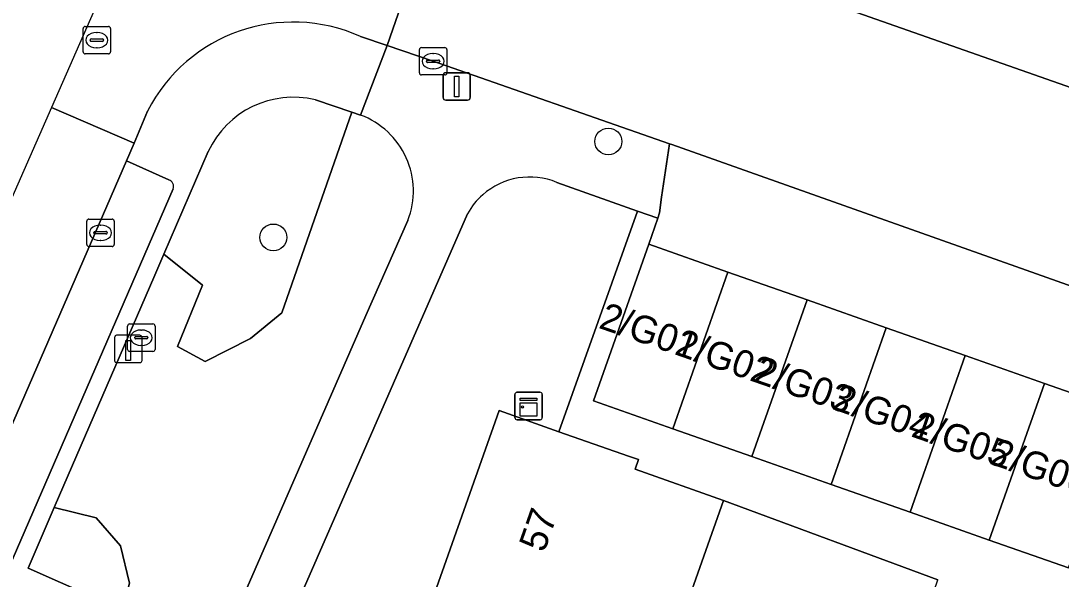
# Model space of a CAD drawing. Extents: x 163266 to 164362, y 381528 to 382286.
# Drawn here: x 163663.56 to 163701.49, y 381798.56 to 381818.93 of the extents above; entities that cross this region are included whole.
import ezdxf

# ---------------------------------------------------------------- set-up
doc = ezdxf.new("R2010")
doc.units = 0
for name, color, linetype in [('IMGEO_Boom', 7, 'Continuous'), ('IMGEO_Erf', 7, 'Continuous'), ('IMGEO_Groenvoorziening', 7, 'Continuous'), ('IMGEO_Kast', 7, 'Continuous'), ('IMGEO_Kolk', 7, 'Continuous'), ('IMGEO_Laadpaal', 7, 'Continuous'), ('IMGEO_Lichtmast', 7, 'Continuous'), ('IMGEO_Pand', 7, 'Continuous'), ('IMGEO_Pand_nummerreeks', 7, 'Continuous'), ('IMGEO_Parkeervlak_open', 7, 'Continuous'), ('IMGEO_Rijbaan_lokaal_open', 7, 'Continuous'), ('IMGEO_Rioolput', 7, 'Continuous'), ('IMGEO_Voetpad_open', 7, 'Continuous')]:
    doc.layers.add(name, color=color, linetype=linetype)

msp = doc.modelspace()

# ---------------------------------------------------------------- linework, layer by layer
at = {"layer": 'IMGEO_Boom'}
for centre in [(163684.985, 381814.526), (163672.771, 381811.027)]:
    msp.add_circle(centre, 0.489, dxfattribs=at)
at = {"layer": 'IMGEO_Erf'}
for points in [[(163666.153, 381762.56), (163668.236, 381768.474), (163670.319, 381774.388), (163672.403, 381780.302), (163674.486, 381786.216), (163676.569, 381792.13), (163678.652, 381798.043), (163681.001, 381804.712), (163683.186, 381803.942), (163686.047, 381811.989), (163683.111, 381813.033)], [(163679.851, 381811.893), (163653.323, 381751.193), (163653.198, 381750)], [(163689.96, 381777.195), (163692.927, 381776.181), (163695.11, 381782.57), (163692.014, 381783.644), (163692.619, 381785.386), (163692.838, 381786.018), (163692.983, 381786.435), (163693.974, 381789.288), (163697.139, 381788.189), (163697.285, 381788.135), (163699.434, 381794.32), (163695.961, 381795.52), (163697.003, 381798.534), (163689.18, 381801.438), (163686.959, 381795.132), (163684.876, 381789.218), (163682.793, 381783.305), (163680.71, 381777.391), (163678.626, 381771.476), (163676.543, 381765.562)]]:
    msp.add_lwpolyline(points, dxfattribs=at)
for centre, radius, start, end in [((163682.119, 381810.637), 2.593, 67.5074, 131.4104), ((163682.13, 381810.63), 2.606, 131.4888, 151.0092)]:
    msp.add_arc(centre, radius, start, end, dxfattribs=at)
at = {"layer": 'IMGEO_Groenvoorziening'}
for points in [[(163675.631, 381815.598), (163674.306, 381816.042)], [(163675.953, 381815.49), (163675.631, 381815.598), (163673.083, 381808.276), (163671.945, 381807.337), (163670.285, 381806.507), (163669.274, 381807.048), (163670.194, 381809.286), (163668.78, 381810.415), (163668.449, 381809.65), (163664.786, 381801.179), (163666.314, 381800.803), (163667.198, 381799.774), (163667.523, 381798.42), (163667.255, 381797.445), (163670.736, 381795.905), (163671.522, 381797.593), (163676.148, 381808.181)], [(163670.398, 381814.16), (163668.78, 381810.415), (163670.194, 381809.286), (163669.274, 381807.048), (163670.285, 381806.507), (163671.945, 381807.337), (163673.083, 381808.276), (163675.631, 381815.598)], [(163676.148, 381808.181), (163677.678, 381811.648)]]:
    msp.add_lwpolyline(points, dxfattribs=at)
msp.add_lwpolyline([(163664.786, 381801.179), (163663.828, 381798.962), (163667.255, 381797.445), (163667.523, 381798.42), (163667.198, 381799.774), (163666.314, 381800.803)], close=True, dxfattribs=at)
for centre, radius, start, end in [((163673.501, 381812.714), 3.424, 76.4087, 155.02), ((163674.914, 381812.715), 2.963, 338.8846, 69.4742)]:
    msp.add_arc(centre, radius, start, end, dxfattribs=at)
at = {"layer": 'IMGEO_Kast'}
for p, q in [((163681.577, 381804.454), (163681.577, 381805.295)), ((163681.577, 381805.295), (163681.577, 381804.454)), ((163681.652, 381805.379), (163682.493, 381805.379)), ((163682.493, 381805.379), (163681.652, 381805.379)), ((163682.577, 381805.304), (163682.577, 381804.463)), ((163682.577, 381804.463), (163682.577, 381805.304)), ((163682.502, 381804.379), (163681.661, 381804.379)), ((163681.661, 381804.379), (163682.502, 381804.379))]:
    msp.add_line(p, q, dxfattribs=at)
for points in [[(163681.772, 381805.169), (163682.372, 381805.169), (163682.372, 381805.084), (163681.772, 381805.084), (163681.772, 381805.169)], [(163681.772, 381804.994), (163682.372, 381804.994), (163682.372, 381804.505), (163681.772, 381804.505), (163681.772, 381804.994)]]:
    msp.add_lwpolyline(points, dxfattribs=at)
msp.add_circle((163681.856, 381804.843), 0.0377, dxfattribs=at)
for centre, start, end in [((163681.655, 381805.301), 92.4484, 184.2845), ((163681.655, 381805.301), 92.4484, 184.2845), ((163682.499, 381805.301), 2.4484, 94.2845), ((163682.499, 381805.301), 2.4484, 94.2845), ((163681.655, 381804.457), 182.4484, 274.2845), ((163681.655, 381804.457), 182.4484, 274.2845), ((163682.499, 381804.457), 272.4484, 4.2845), ((163682.499, 381804.457), 272.4484, 4.2845)]:
    msp.add_arc(centre, 0.0779, start, end, dxfattribs=at)
at = {"layer": 'IMGEO_Kolk'}
for p, q in [((163678.096, 381817.026), (163678.096, 381817.878)), ((163678.171, 381817.952), (163679.023, 381817.952)), ((163679.097, 381817.878), (163679.097, 381817.026)), ((163678.355, 381817.446), (163678.355, 381817.458)), ((163678.793, 381817.409), (163678.395, 381817.409)), ((163678.398, 381817.495), (163678.796, 381817.495)), ((163678.584, 381817.732), (163678.609, 381817.732)), ((163678.839, 381817.458), (163678.839, 381817.446)), ((163678.607, 381817.172), (163678.582, 381817.172)), ((163679.023, 381816.952), (163678.171, 381816.952)), ((163666.045, 381811.696), (163666.897, 381811.696)), ((163665.97, 381810.77), (163665.97, 381811.622)), ((163666.458, 381811.476), (163666.483, 381811.476)), ((163666.971, 381811.622), (163666.971, 381810.77)), ((163666.229, 381811.19), (163666.229, 381811.202)), ((163666.667, 381811.153), (163666.269, 381811.153)), ((163666.272, 381811.239), (163666.67, 381811.239)), ((163666.713, 381811.202), (163666.713, 381811.19)), ((163666.897, 381810.696), (163666.045, 381810.696)), ((163666.481, 381810.916), (163666.456, 381810.916)), ((163667.457, 381806.944), (163667.457, 381807.796)), ((163667.532, 381807.87), (163668.384, 381807.87)), ((163667.945, 381807.65), (163667.97, 381807.65)), ((163668.458, 381807.796), (163668.458, 381806.944)), ((163667.716, 381807.364), (163667.716, 381807.376)), ((163668.154, 381807.327), (163667.756, 381807.327)), ((163667.759, 381807.413), (163668.157, 381807.413)), ((163668.2, 381807.376), (163668.2, 381807.364)), ((163668.384, 381806.87), (163667.532, 381806.87)), ((163667.968, 381807.09), (163667.943, 381807.09))]:
    msp.add_line(p, q, dxfattribs=at)
for points in [[(163678.096, 381817.026), (163678.096, 381817.878)], [(163678.171, 381817.952), (163679.023, 381817.952)], [(163679.097, 381817.878), (163679.097, 381817.026)], [(163679.023, 381816.952), (163678.171, 381816.952)], [(163666.045, 381811.696), (163666.897, 381811.696)], [(163665.97, 381810.77), (163665.97, 381811.622)], [(163666.971, 381811.622), (163666.971, 381810.77)], [(163666.897, 381810.696), (163666.045, 381810.696)], [(163667.457, 381806.944), (163667.457, 381807.796)], [(163667.532, 381807.87), (163668.384, 381807.87)], [(163668.458, 381807.796), (163668.458, 381806.944)], [(163668.384, 381806.87), (163667.532, 381806.87)]]:
    msp.add_lwpolyline(points, dxfattribs=at)
for centre, radius, start, end in [((163678.173, 381817.876), 0.0765, 91.552, 178.448), ((163678.173, 381817.876), 0.0765, 91.552, 178.448), ((163679.021, 381817.876), 0.0765, 1.552, 88.448), ((163679.021, 381817.876), 0.0765, 1.552, 88.448), ((163678.395, 381817.455), 0.0403, 85.8775, 175.7526), ((163678.392, 381817.445), 0.0366, 178.938, 274.7102), ((163678.796, 381817.452), 0.043, 264.8664, 352.4533), ((163678.8, 381817.457), 0.0386, 1.7309, 96.639), ((163678.173, 381817.028), 0.0765, 181.552, 268.448), ((163678.173, 381817.028), 0.0765, 181.552, 268.448), ((163679.021, 381817.028), 0.0765, 271.552, 358.448), ((163679.021, 381817.028), 0.0765, 271.552, 358.448), ((163666.047, 381811.62), 0.0765, 91.552, 178.448), ((163666.047, 381811.62), 0.0765, 91.552, 178.448), ((163666.895, 381811.62), 0.0765, 1.552, 88.448), ((163666.895, 381811.62), 0.0765, 1.552, 88.448), ((163666.269, 381811.199), 0.0403, 85.8775, 175.7526), ((163666.266, 381811.189), 0.0366, 178.938, 274.7102), ((163666.67, 381811.196), 0.043, 264.8664, 352.4533), ((163666.674, 381811.201), 0.0386, 1.7309, 96.639), ((163666.047, 381810.772), 0.0765, 181.552, 268.448), ((163666.047, 381810.772), 0.0765, 181.552, 268.448), ((163666.895, 381810.772), 0.0765, 271.552, 358.448), ((163666.895, 381810.772), 0.0765, 271.552, 358.448), ((163667.534, 381807.794), 0.0765, 91.552, 178.448), ((163667.534, 381807.794), 0.0765, 91.552, 178.448), ((163668.382, 381807.794), 0.0765, 1.552, 88.448), ((163668.382, 381807.794), 0.0765, 1.552, 88.448), ((163667.756, 381807.373), 0.0403, 85.8775, 175.7526), ((163667.753, 381807.363), 0.0366, 178.938, 274.7102), ((163668.157, 381807.37), 0.043, 264.8664, 352.4533), ((163668.161, 381807.375), 0.0386, 1.7309, 96.639), ((163667.534, 381806.946), 0.0765, 181.552, 268.448), ((163667.534, 381806.946), 0.0765, 181.552, 268.448), ((163668.382, 381806.946), 0.0765, 271.552, 358.448), ((163668.382, 381806.946), 0.0765, 271.552, 358.448)]:
    msp.add_arc(centre, radius, start, end, dxfattribs=at)
for centre, major_axis, ratio, start_param, end_param in [((163678.583, 381817.452), (-0.387, 0.002), 0.722429, 4.712389, 7.853982), ((163678.608, 381817.452), (-0.39, 0.002), 0.717154, 1.570796, 4.712389), ((163666.457, 381811.196), (-0.387, 0.002), 0.722429, 4.712389, 7.853982), ((163666.482, 381811.196), (-0.39, 0.002), 0.717154, 1.570796, 4.712389), ((163667.944, 381807.37), (-0.387, 0.002), 0.722429, 4.712389, 7.853982), ((163667.969, 381807.37), (-0.39, 0.002), 0.717154, 1.570796, 4.712389)]:
    msp.add_ellipse(centre, major_axis=major_axis, ratio=ratio, start_param=start_param, end_param=end_param, dxfattribs=at)
at = {"layer": 'IMGEO_Laadpaal'}
for p, q in [((163666.984, 381807.376), (163666.984, 381806.535)), ((163666.984, 381807.376), (163666.984, 381806.535)), ((163667.9, 381807.46), (163667.059, 381807.46)), ((163667.9, 381807.46), (163667.059, 381807.46)), ((163667.984, 381806.544), (163667.984, 381807.385)), ((163667.984, 381806.544), (163667.984, 381807.385)), ((163667.068, 381806.46), (163667.909, 381806.46)), ((163667.068, 381806.46), (163667.909, 381806.46))]:
    msp.add_line(p, q, dxfattribs=at)
msp.add_lwpolyline([(163667.399, 381807.273), (163667.559, 381807.273), (163667.559, 381806.54), (163667.399, 381806.54), (163667.399, 381807.273)], dxfattribs=at)
for centre, start, end in [((163667.062, 381807.382), 92.4484, 184.2845), ((163667.062, 381807.382), 92.4484, 184.2845), ((163667.906, 381807.382), 2.4484, 94.2845), ((163667.906, 381807.382), 2.4484, 94.2845), ((163667.062, 381806.538), 182.4484, 274.2845), ((163667.062, 381806.538), 182.4484, 274.2845), ((163667.906, 381806.538), 272.4484, 4.2845), ((163667.906, 381806.538), 272.4484, 4.2845)]:
    msp.add_arc(centre, 0.0779, start, end, dxfattribs=at)
at = {"layer": 'IMGEO_Lichtmast'}
for p, q in [((163679.06, 381817.033), (163679.85, 381817.033)), ((163679.85, 381817.033), (163679.06, 381817.033)), ((163678.96, 381816.133), (163678.96, 381816.933)), ((163678.96, 381816.933), (163678.96, 381816.133)), ((163679.95, 381816.933), (163679.95, 381816.133)), ((163679.95, 381816.133), (163679.95, 381816.933)), ((163679.85, 381816.033), (163679.06, 381816.033)), ((163679.06, 381816.033), (163679.85, 381816.033))]:
    msp.add_line(p, q, dxfattribs=at)
msp.add_lwpolyline([(163679.38, 381816.908), (163679.53, 381816.908), (163679.53, 381816.158), (163679.38, 381816.158), (163679.38, 381816.908)], dxfattribs=at)
for centre, start, end in [((163679.06, 381816.933), 90, 180), ((163679.06, 381816.933), 90, 180), ((163679.85, 381816.933), 0, 90), ((163679.85, 381816.933), 360, 90), ((163679.06, 381816.133), 180, 270), ((163679.06, 381816.133), 180, 270), ((163679.85, 381816.133), 270, 0), ((163679.85, 381816.133), 270, 0)]:
    msp.add_arc(centre, 0.1, start, end, dxfattribs=at)
at = {"layer": 'IMGEO_Pand'}
for points in [[(163687.333, 381804.05), (163689.345, 381809.763), (163686.459, 381810.779), (163684.448, 381805.066)], [(163690.219, 381803.034), (163692.23, 381808.748), (163689.345, 381809.763), (163687.333, 381804.05)], [(163693.104, 381802.019), (163695.115, 381807.732), (163692.23, 381808.748), (163690.219, 381803.034)], [(163693.104, 381802.019), (163695.989, 381801.003), (163698, 381806.716), (163695.115, 381807.732)], [(163698, 381806.716), (163695.989, 381801.003), (163698.874, 381799.987), (163700.886, 381805.701)], [(163701.76, 381798.972), (163703.771, 381804.685), (163700.886, 381805.701), (163698.874, 381799.987)], [(163689.18, 381801.438), (163685.957, 381802.573), (163686.08, 381802.923), (163685.717, 381803.051), (163683.186, 381803.942), (163681.001, 381804.712), (163678.652, 381798.043), (163686.959, 381795.132)]]:
    msp.add_lwpolyline(points, close=True, dxfattribs=at)
at = {"layer": 'IMGEO_Parkeervlak_open'}
for points in [[(163667.414, 381813.825), (163642.095, 381755.459), (163643.689, 381754.793)], [(163668.962, 381813.124), (163667.414, 381813.825)], [(163644.035, 381754.962), (163669.114, 381812.797)]]:
    msp.add_lwpolyline(points, dxfattribs=at)
msp.add_arc((163668.892, 381812.893), 0.242, 336.7507, 73.1103, dxfattribs=at)
at = {"layer": 'IMGEO_Rijbaan_lokaal_open'}
for points in [[(163672.403, 381833.576), (163669.086, 381825.786), (163664.687, 381815.77), (163667.695, 381814.465), (163668.182, 381815.637)], [(163675.949, 381818.355), (163676.919, 381818.032), (163679.157, 381824.486), (163678.279, 381824.794)]]:
    msp.add_lwpolyline(points, dxfattribs=at)
for points in [[(163704.639, 381815.509), (163685.076, 381822.394), (163681.989, 381823.48), (163681.044, 381823.833), (163679.157, 381824.486), (163676.919, 381818.032), (163678.597, 381817.452), (163687.218, 381814.444), (163687.304, 381814.414), (163703.06, 381808.819), (163722.904, 381801.849), (163723.746, 381801.558), (163726.041, 381807.998), (163720.044, 381810.112)], [(163638.435, 381756.318), (163641.914, 381755.03), (163642.095, 381755.459), (163667.414, 381813.825), (163667.695, 381814.465), (163664.687, 381815.77), (163647.393, 381776.397)]]:
    msp.add_lwpolyline(points, close=True, dxfattribs=at)
msp.add_arc((163673.499, 381812.901), 5.979, 65.8059, 152.7683, dxfattribs=at)
at = {"layer": 'IMGEO_Rioolput'}
for p, q in [((163665.835, 381817.795), (163665.835, 381818.647)), ((163665.91, 381818.721), (163666.762, 381818.721)), ((163666.836, 381818.647), (163666.836, 381817.795)), ((163666.094, 381818.215), (163666.094, 381818.227)), ((163666.532, 381818.178), (163666.134, 381818.178)), ((163666.137, 381818.264), (163666.535, 381818.264)), ((163666.323, 381818.501), (163666.348, 381818.501)), ((163666.578, 381818.227), (163666.578, 381818.215)), ((163666.346, 381817.941), (163666.321, 381817.941)), ((163666.762, 381817.721), (163665.91, 381817.721))]:
    msp.add_line(p, q, dxfattribs=at)
for points in [[(163665.835, 381817.795), (163665.835, 381818.647)], [(163665.91, 381818.721), (163666.762, 381818.721)], [(163666.836, 381818.647), (163666.836, 381817.795)], [(163666.762, 381817.721), (163665.91, 381817.721)]]:
    msp.add_lwpolyline(points, dxfattribs=at)
for centre, radius, start, end in [((163665.912, 381818.645), 0.0765, 91.552, 178.448), ((163665.912, 381818.645), 0.0765, 91.552, 178.448), ((163666.76, 381818.645), 0.0765, 1.552, 88.448), ((163666.76, 381818.645), 0.0765, 1.552, 88.448), ((163666.134, 381818.224), 0.0403, 85.8775, 175.7526), ((163666.131, 381818.214), 0.0366, 178.938, 274.7102), ((163666.535, 381818.221), 0.043, 264.8664, 352.4533), ((163666.539, 381818.226), 0.0386, 1.7309, 96.639), ((163665.912, 381817.797), 0.0765, 181.552, 268.448), ((163665.912, 381817.797), 0.0765, 181.552, 268.448), ((163666.76, 381817.797), 0.0765, 271.552, 358.448), ((163666.76, 381817.797), 0.0765, 271.552, 358.448)]:
    msp.add_arc(centre, radius, start, end, dxfattribs=at)
for centre, major_axis, ratio, start_param, end_param in [((163666.322, 381818.221), (-0.387, 0.002), 0.722429, 4.712389, 7.853982), ((163666.347, 381818.221), (-0.39, 0.002), 0.717154, 1.570796, 4.712389)]:
    msp.add_ellipse(centre, major_axis=major_axis, ratio=ratio, start_param=start_param, end_param=end_param, dxfattribs=at)
at = {"layer": 'IMGEO_Voetpad_open'}
for points in [[(163686.577, 381826.945), (163685.646, 381824.121), (163685.076, 381822.394), (163704.639, 381815.509), (163720.044, 381810.112), (163726.041, 381807.998), (163740.853, 381802.813), (163758.246, 381796.703), (163758.267, 381796.696), (163759.961, 381796.019), (163778.368, 381789.58), (163800.522, 381781.766), (163810.767, 381778.175), (163816.213, 381776.322), (163816.626, 381777.354), (163822.318, 381775.342), (163821.983, 381774.359), (163832.755, 381770.426)], [(163674.306, 381816.042), (163675.631, 381815.598), (163675.953, 381815.49), (163676.919, 381818.032), (163675.949, 381818.355)], [(163683.111, 381813.033), (163686.047, 381811.989), (163686.787, 381811.726), (163686.854, 381811.92), (163686.921, 381812.493), (163687.218, 381814.444), (163678.597, 381817.452), (163676.919, 381818.032), (163675.953, 381815.49)], [(163668.182, 381815.637), (163667.695, 381814.465), (163667.414, 381813.825), (163668.962, 381813.124)], [(163644.651, 381754.746), (163645.084, 381755.742), (163648.873, 381764.447), (163651.365, 381770.102), (163651.958, 381771.509), (163657.922, 381785.206), (163658.074, 381785.559), (163663.271, 381797.586), (163666.67, 381796.073), (163667.255, 381797.445), (163663.828, 381798.962), (163664.786, 381801.179), (163668.449, 381809.65), (163668.78, 381810.415), (163670.398, 381814.16)], [(163669.114, 381812.797), (163644.035, 381754.962)], [(163653.198, 381750), (163653.323, 381751.193), (163679.851, 381811.893)], [(163701.76, 381798.972), (163698.874, 381799.987), (163695.989, 381801.003), (163693.104, 381802.019), (163690.219, 381803.034), (163687.333, 381804.05), (163684.448, 381805.066), (163686.459, 381810.779), (163686.787, 381811.726), (163686.047, 381811.989), (163683.186, 381803.942), (163685.717, 381803.051), (163686.08, 381802.923), (163685.957, 381802.573), (163689.18, 381801.438), (163697.003, 381798.534)], [(163677.678, 381811.648), (163676.148, 381808.181), (163671.522, 381797.593), (163670.736, 381795.905), (163667.255, 381797.445), (163666.67, 381796.073), (163670.212, 381794.497), (163669.214, 381792.364), (163661.227, 381773.927), (163658.866, 381768.438), (163651.958, 381771.509)]]:
    msp.add_lwpolyline(points, dxfattribs=at)
msp.add_lwpolyline([(163687.218, 381814.444), (163686.921, 381812.493), (163686.854, 381811.92), (163686.787, 381811.726), (163686.459, 381810.779), (163689.345, 381809.763), (163692.23, 381808.748), (163695.115, 381807.732), (163698, 381806.716), (163700.886, 381805.701), (163703.771, 381804.685), (163706.656, 381803.669), (163709.541, 381802.654), (163712.427, 381801.638), (163715.312, 381800.622), (163718.197, 381799.606), (163721.082, 381798.591), (163721.386, 381799.437), (163721.492, 381799.731), (163722.904, 381801.849), (163703.06, 381808.819), (163687.304, 381814.414)], close=True, dxfattribs=at)
for centre, radius, start, end in [((163673.499, 381812.901), 5.979, 65.8059, 152.7683), ((163673.501, 381812.714), 3.424, 76.4087, 155.02), ((163674.914, 381812.715), 2.963, 338.8846, 69.4742), ((163682.119, 381810.637), 2.593, 67.5074, 131.4104), ((163668.892, 381812.893), 0.242, 336.7507, 73.1103), ((163682.13, 381810.63), 2.606, 131.4888, 151.0092)]:
    msp.add_arc(centre, radius, start, end, dxfattribs=at)

# ---------------------------------------------------------------- texts
at = {"layer": 'IMGEO_Pand_nummerreeks'}
for s, rotation, p in [('2/G01', 340.8411, (163684.594, 381807.737)), ('2/G02', 340.8411, (163687.357, 381806.777)), ('2/G03', 340.8411, (163690.237, 381805.777)), ('2/G04', 340.8411, (163693.11, 381804.778)), ('2/G05', 340.8411, (163695.983, 381803.78)), ('2/G06', 340.8411, (163698.857, 381802.782)), ('57', 70.5941, (163682.644, 381799.503))]:
    msp.add_text(s, height=1, rotation=rotation, dxfattribs=at).set_placement(p)

doc.saveas('drawing.dxf')
